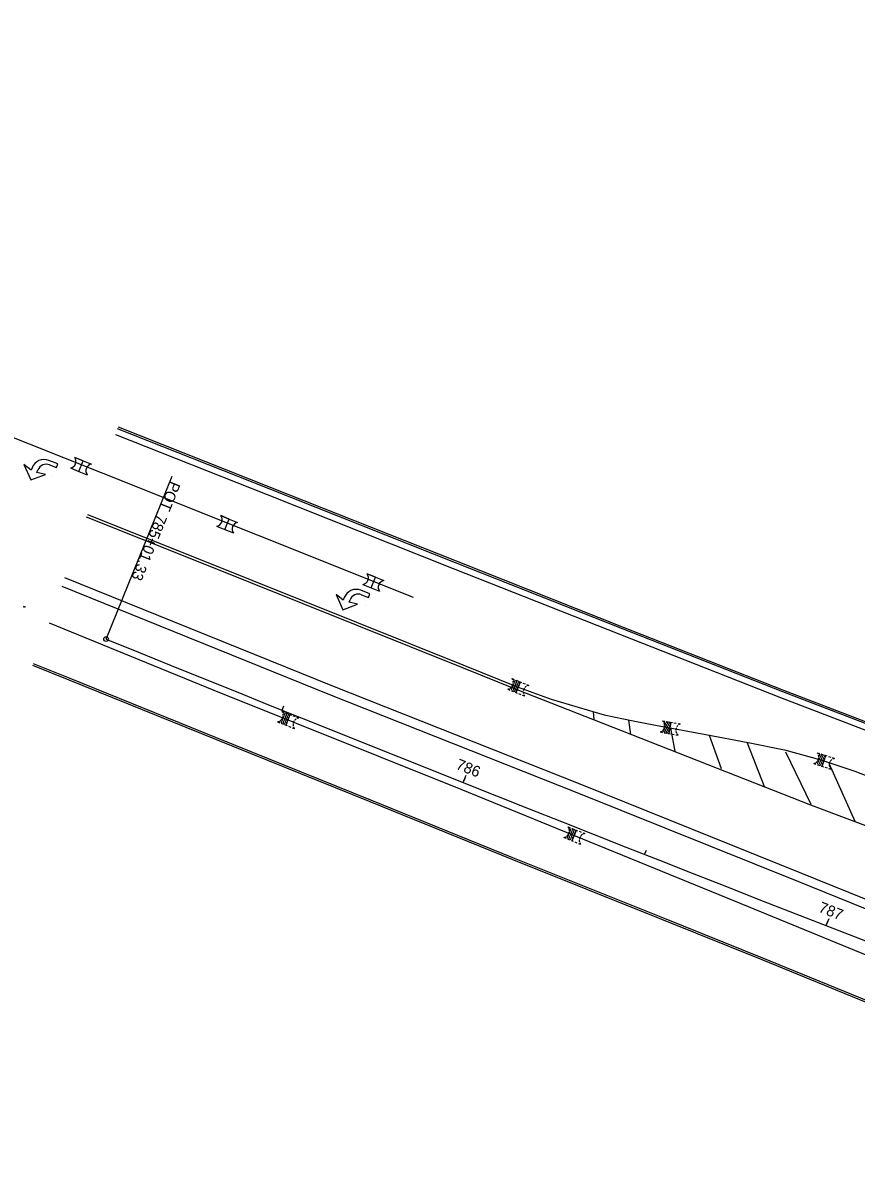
# Model space of a CAD drawing. Extents: x 2349621 to 2352073, y 625611 to 626553.
# Drawn here: x 2350953.7 to 2351167.3, y 625866.1 to 626159.2 of the extents above; entities that cross this region are included whole.
import ezdxf

# ---------------------------------------------------------------- set-up
doc = ezdxf.new("R2010")
doc.units = 0
for name, color, linetype in [('DR_P_Storm_Sewer', 7, 'Continuous'), ('MT_P_Dotted_Line', 7, 'Continuous'), ('PM_X_Cells', 7, 'Continuous'), ('PM_X_Channelizing_Line', 7, 'Continuous'), ('PM_X_Edge_Line', 7, 'Continuous'), ('PM_X_Lane_Line', 7, 'Continuous'), ('PV_X_Curb', 7, 'Continuous'), ('PV_X_EOP', 7, 'Continuous'), ('RW_X_CL', 7, 'Continuous'), ('RW_X_CL_1000_Cardinal_Points', 7, 'Continuous'), ('RW_X_CL_100_Cardinal_Points', 7, 'Continuous'), ('RW_X_CL_100_Stations', 7, 'Continuous'), ('RW_X_CL_500_Cardinal_Points', 7, 'Continuous'), ('RW_X_CL_500_Stations', 7, 'Continuous')]:
    doc.layers.add(name, color=color, linetype=linetype)

msp = doc.modelspace()

# ---------------------------------------------------------------- linework, layer by layer
at = {"layer": 'DR_P_Storm_Sewer'}
for p, q in [((2350953.99, 626046.04), (2350953.99, 626046.04)), ((2350955.83, 626044.6), (2350953.99, 626046.04)), ((2350953.99, 626046.04), (2350955.72, 626042.14)), ((2350962.66, 626046.21), (2350960.35, 626047.12)), ((2350960.56, 626045.97), (2350962.29, 626045.28)), ((2350962.29, 626045.28), (2350962.66, 626046.21)), ((2350969.15, 626047.03), (2350967.01, 626047.9)), ((2350967.01, 626047.9), (2350969.15, 626047.03)), ((2350968.05, 626044.31), (2350969.15, 626047.03)), ((2350969.15, 626047.03), (2350971.3, 626046.16)), ((2350955.72, 626042.14), (2350959.53, 626043.51)), ((2350956.08, 626045.22), (2350955.83, 626044.6)), ((2350957.32, 626044.02), (2350957.58, 626044.67)), ((2350959.53, 626043.51), (2350957.32, 626044.02)), ((2350961.43, 626043.11), (2350961.43, 626043.11)), ((2350965.91, 626045.18), (2350968.05, 626044.31)), ((2350965.91, 626045.18), (2350968.05, 626044.31)), ((2350968.05, 626044.31), (2350970.2, 626043.44)), ((2351006.63, 626032.1), (2351004.48, 626032.97)), ((2351004.48, 626032.97), (2351006.63, 626032.1)), ((2351005.52, 626029.39), (2351006.63, 626032.1)), ((2351006.63, 626032.1), (2351008.77, 626031.23)), ((2351003.38, 626030.26), (2351005.52, 626029.39)), ((2351003.38, 626030.26), (2351005.52, 626029.39)), ((2351005.52, 626029.39), (2351007.67, 626028.52)), ((2351044.1, 626017.18), (2351041.95, 626018.05)), ((2351041.95, 626018.05), (2351044.1, 626017.18)), ((2351043, 626014.46), (2351044.1, 626017.18)), ((2351044.1, 626017.18), (2351046.24, 626016.31)), ((2351042.66, 626012.95), (2351040.36, 626013.86)), ((2351040.85, 626015.33), (2351043, 626014.46)), ((2351040.85, 626015.33), (2351043, 626014.46)), ((2351043, 626014.46), (2351045.14, 626013.59)), ((2351034, 626012.78), (2351034, 626012.78)), ((2351035.84, 626011.34), (2351034, 626012.78)), ((2351034, 626012.78), (2351035.73, 626008.88)), ((2351036.08, 626011.96), (2351035.84, 626011.34)), ((2351037.33, 626010.76), (2351037.59, 626011.41)), ((2351039.53, 626010.25), (2351037.33, 626010.76)), ((2351040.56, 626012.71), (2351042.3, 626012.02)), ((2351042.3, 626012.02), (2351042.66, 626012.95)), ((2351035.73, 626008.88), (2351039.53, 626010.25)), ((2351041.44, 626009.85), (2351041.44, 626009.85))]:
    msp.add_line(p, q, dxfattribs=at)
for centre, radius, start, end in [((2350959.15, 626044.07), 3.28, 68.5035, 159.412), ((2350959.71, 626043.83), 2.3, 68.5035, 158.5035), ((2350965.61, 626046.88), 1.73, 279.8966, 35.9489), ((2350965.61, 626046.88), 1.73, 279.8966, 35.9489), ((2350971.59, 626044.46), 1.73, 99.8966, 215.9489), ((2351003.08, 626031.96), 1.73, 279.8966, 35.9489), ((2351003.08, 626031.96), 1.73, 279.8966, 35.9489), ((2351009.07, 626029.53), 1.73, 99.8966, 215.9489), ((2351040.56, 626017.03), 1.73, 279.8966, 35.9489), ((2351040.56, 626017.03), 1.73, 279.8966, 35.9489), ((2351039.16, 626010.81), 3.28, 68.5035, 159.412), ((2351046.54, 626014.61), 1.73, 99.8966, 215.9489), ((2351039.72, 626010.57), 2.3, 68.5035, 158.5035)]:
    msp.add_arc(centre, radius, start, end, dxfattribs=at)
at = {"layer": 'MT_P_Dotted_Line'}
msp.add_lwpolyline([(2350689.08, 626159.18), (2350751.11, 626134.18), (2350853.61, 626092.56), (2350906.16, 626071.18), (2350945.59, 626055.2), (2350974.18, 626043.81), (2351053.76, 626012.11)], dxfattribs=at)
at = {"layer": 'PM_X_Cells'}
for p, q in [((2351042.66, 626012.95), (2351040.36, 626013.86)), ((2351034, 626012.78), (2351034, 626012.78)), ((2351035.84, 626011.34), (2351034, 626012.78)), ((2351034, 626012.78), (2351035.73, 626008.88)), ((2351036.08, 626011.96), (2351035.84, 626011.34)), ((2351037.33, 626010.76), (2351037.59, 626011.41)), ((2351039.53, 626010.25), (2351037.33, 626010.76)), ((2351040.56, 626012.71), (2351042.3, 626012.02)), ((2351042.3, 626012.02), (2351042.66, 626012.95)), ((2350953.75, 626009.79), (2350954.31, 626009.57)), ((2351035.73, 626008.88), (2351039.53, 626010.25)), ((2351041.44, 626009.85), (2351041.44, 626009.85)), ((2351079.12, 625991.22), (2351079.67, 625991)), ((2351080.54, 625988.58), (2351079.49, 625991.07)), ((2351080.05, 625990.84), (2351080.61, 625990.62)), ((2351080.8, 625989.21), (2351080.12, 625990.82)), ((2351080.16, 625987.64), (2351081.26, 625990.35)), ((2351081.05, 625989.83), (2351080.74, 625990.56)), ((2351080.98, 625990.46), (2351081.54, 625990.24)), ((2351078.02, 625988.51), (2351078.57, 625988.28)), ((2351078.59, 625988.27), (2351078.43, 625988.63)), ((2351079.22, 625988.02), (2351078.84, 625988.9)), ((2351078.95, 625988.13), (2351079.51, 625987.9)), ((2351079.84, 625987.76), (2351079.19, 625989.3)), ((2351080.29, 625987.95), (2351079.43, 625989.97)), ((2351079.88, 625987.75), (2351080.44, 625987.52)), ((2351080.71, 625988.99), (2351080.71, 625988.99)), ((2351080.81, 625987.37), (2351081.37, 625987.15)), ((2351081.92, 625990.09), (2351082.47, 625989.86)), ((2351082.85, 625989.71), (2351083.4, 625989.48)), ((2351081.75, 625986.99), (2351082.3, 625986.77)), ((2351020.12, 625982.87), (2351020.68, 625982.65)), ((2351020.12, 625982.87), (2351020.68, 625982.65)), ((2351021.29, 625979.6), (2351020.44, 625981.62)), ((2351021.29, 625979.6), (2351020.44, 625981.62)), ((2351021.55, 625980.23), (2351020.49, 625982.72)), ((2351021.55, 625980.23), (2351020.49, 625982.72)), ((2351021.06, 625982.49), (2351021.61, 625982.27)), ((2351021.06, 625982.49), (2351021.61, 625982.27)), ((2351021.8, 625980.86), (2351021.12, 625982.47)), ((2351021.8, 625980.86), (2351021.12, 625982.47)), ((2351021.17, 625979.29), (2351022.27, 625982)), ((2351021.17, 625979.29), (2351022.27, 625982)), ((2351022.06, 625981.49), (2351021.75, 625982.21)), ((2351022.06, 625981.49), (2351021.75, 625982.21)), ((2351021.99, 625982.12), (2351022.55, 625981.89)), ((2351021.99, 625982.12), (2351022.55, 625981.89)), ((2351022.92, 625981.74), (2351023.48, 625981.51)), ((2351022.92, 625981.74), (2351023.48, 625981.51)), ((2351019.02, 625980.16), (2351019.58, 625979.93)), ((2351019.02, 625980.16), (2351019.58, 625979.93)), ((2351019.59, 625979.93), (2351019.44, 625980.29)), ((2351019.59, 625979.93), (2351019.44, 625980.29)), ((2351020.22, 625979.67), (2351019.85, 625980.55)), ((2351020.22, 625979.67), (2351019.85, 625980.55)), ((2351019.96, 625979.78), (2351020.51, 625979.55)), ((2351019.96, 625979.78), (2351020.51, 625979.55)), ((2351020.85, 625979.42), (2351020.2, 625980.96)), ((2351020.85, 625979.42), (2351020.2, 625980.96)), ((2351020.89, 625979.4), (2351021.44, 625979.18)), ((2351020.89, 625979.4), (2351021.44, 625979.18)), ((2351021.72, 625980.65), (2351021.72, 625980.65)), ((2351021.72, 625980.65), (2351021.72, 625980.65)), ((2351021.82, 625979.02), (2351022.38, 625978.8)), ((2351021.82, 625979.02), (2351022.38, 625978.8)), ((2351022.75, 625978.64), (2351023.31, 625978.42)), ((2351022.75, 625978.64), (2351023.31, 625978.42)), ((2351023.85, 625981.36), (2351024.41, 625981.13)), ((2351023.85, 625981.36), (2351024.41, 625981.13)), ((2351117.66, 625980.43), (2351118.25, 625980.32)), ((2351119.59, 625978.13), (2351118.05, 625980.36)), ((2351119.07, 625977.19), (2351118.12, 625978.57)), ((2351119.47, 625977.46), (2351118.22, 625979.27)), ((2351118.65, 625980.25), (2351119.24, 625980.14)), ((2351119.71, 625978.8), (2351118.72, 625980.23)), ((2351119.83, 625979.46), (2351119.39, 625980.11)), ((2351119.41, 625977.13), (2351119.93, 625980.01)), ((2351119.64, 625980.06), (2351120.23, 625979.96)), ((2351119.67, 625978.57), (2351119.67, 625978.57)), ((2351120.63, 625979.88), (2351121.22, 625979.77)), ((2351121.62, 625979.7), (2351122.21, 625979.59)), ((2351117.13, 625977.55), (2351117.72, 625977.44)), ((2351117.73, 625977.43), (2351117.51, 625977.76)), ((2351118.4, 625977.31), (2351117.86, 625978.1)), ((2351118.12, 625977.36), (2351118.71, 625977.26)), ((2351119.11, 625977.18), (2351119.7, 625977.07)), ((2351120.1, 625977), (2351120.69, 625976.89)), ((2351121.09, 625976.82), (2351121.68, 625976.71)), ((2351157.68, 625969.05), (2351157.25, 625969.9)), ((2351157.37, 625972.24), (2351157.94, 625972.05)), ((2351158.32, 625968.84), (2351157.57, 625970.33)), ((2351158.97, 625969.7), (2351157.74, 625972.11)), ((2351158.75, 625969.05), (2351157.76, 625971.01)), ((2351158.32, 625971.92), (2351158.89, 625971.74)), ((2351159.18, 625970.34), (2351158.39, 625971.9)), ((2351158.65, 625968.73), (2351159.56, 625971.52)), ((2351159.39, 625970.99), (2351159.03, 625971.69)), ((2351159.11, 625970.12), (2351159.11, 625970.12)), ((2351159.28, 625971.61), (2351159.85, 625971.42)), ((2351160.23, 625971.3), (2351160.8, 625971.11)), ((2351161.19, 625970.98), (2351161.76, 625970.8)), ((2351156.45, 625969.45), (2351157.02, 625969.27)), ((2351157.03, 625969.26), (2351156.86, 625969.61)), ((2351157.41, 625969.14), (2351157.98, 625968.95)), ((2351158.36, 625968.83), (2351158.93, 625968.64)), ((2351159.32, 625968.51), (2351159.89, 625968.33)), ((2351160.28, 625968.2), (2351160.85, 625968.01)), ((2351093.5, 625953.25), (2351094.05, 625953.03)), ((2351094.92, 625950.61), (2351093.87, 625953.1)), ((2351094.43, 625952.87), (2351094.99, 625952.65)), ((2351095.18, 625951.24), (2351094.5, 625952.85)), ((2351094.54, 625949.67), (2351095.64, 625952.38)), ((2351095.43, 625951.87), (2351095.12, 625952.59)), ((2351095.36, 625952.49), (2351095.92, 625952.27)), ((2351092.4, 625950.54), (2351092.95, 625950.31)), ((2351092.96, 625950.31), (2351092.81, 625950.66)), ((2351093.59, 625950.05), (2351093.22, 625950.93)), ((2351093.33, 625950.16), (2351093.88, 625949.93)), ((2351094.22, 625949.8), (2351093.57, 625951.33)), ((2351094.67, 625949.98), (2351093.81, 625952)), ((2351094.26, 625949.78), (2351094.82, 625949.55)), ((2351095.09, 625951.02), (2351095.09, 625951.02)), ((2351095.19, 625949.4), (2351095.75, 625949.18)), ((2351096.3, 625952.12), (2351096.85, 625951.89)), ((2351097.23, 625951.74), (2351097.78, 625951.51)), ((2351096.13, 625949.02), (2351096.68, 625948.8))]:
    msp.add_line(p, q, dxfattribs=at)
for centre, radius, start, end in [((2351039.16, 626010.81), 3.28, 68.5035, 159.412), ((2351039.72, 626010.57), 2.3, 68.5035, 158.5035), ((2350954.61, 626007.87), 1.73, 99.8966, 115.8391), ((2351077.72, 625990.21), 1.73, 20.0075, 35.9489), ((2351077.72, 625990.21), 1.73, 356.8106, 12.7435), ((2351077.72, 625990.21), 1.73, 279.8966, 295.8433), ((2351077.72, 625990.21), 1.73, 303.101, 319.0339), ((2351077.72, 625990.21), 1.73, 326.3132, 349.543), ((2351083.7, 625987.78), 1.73, 176.81, 192.7435), ((2351083.7, 625987.78), 1.73, 146.3043, 169.5319), ((2351083.7, 625987.78), 1.73, 123.101, 139.0326), ((2351083.7, 625987.78), 1.73, 99.8966, 115.8391), ((2351083.7, 625987.78), 1.73, 200.0045, 215.9489), ((2351018.73, 625981.86), 1.73, 20.0075, 35.9489), ((2351018.73, 625981.86), 1.73, 20.0075, 35.9489), ((2351018.73, 625981.86), 1.73, 326.3132, 349.543), ((2351018.73, 625981.86), 1.73, 326.3132, 349.543), ((2351018.73, 625981.86), 1.73, 356.8106, 12.7435), ((2351018.73, 625981.86), 1.73, 356.8106, 12.7435), ((2351018.73, 625981.86), 1.73, 279.8966, 295.8433), ((2351018.73, 625981.86), 1.73, 279.8966, 295.8433), ((2351018.73, 625981.86), 1.73, 303.101, 319.0339), ((2351018.73, 625981.86), 1.73, 303.101, 319.0339), ((2351024.71, 625979.43), 1.73, 176.81, 192.7435), ((2351024.71, 625979.43), 1.73, 176.81, 192.7435), ((2351024.71, 625979.43), 1.73, 146.3043, 169.5319), ((2351024.71, 625979.43), 1.73, 146.3043, 169.5319), ((2351024.71, 625979.43), 1.73, 200.0045, 215.9489), ((2351024.71, 625979.43), 1.73, 200.0045, 215.9489), ((2351024.71, 625979.43), 1.73, 123.101, 139.0326), ((2351024.71, 625979.43), 1.73, 123.101, 139.0326), ((2351024.71, 625979.43), 1.73, 99.8966, 115.8391), ((2351024.71, 625979.43), 1.73, 99.8966, 115.8391), ((2351116.5, 625979.15), 1.73, 31.6908, 47.6323), ((2351116.5, 625979.15), 1.73, 8.4939, 24.4269), ((2351116.5, 625979.15), 1.73, 337.9965, 1.2263), ((2351122.84, 625977.99), 1.73, 157.9877, 181.2153), ((2351122.84, 625977.99), 1.73, 134.7843, 150.7159), ((2351122.84, 625977.99), 1.73, 111.58, 127.5224), ((2351116.5, 625979.15), 1.73, 291.58, 307.5267), ((2351116.5, 625979.15), 1.73, 314.7843, 330.7172), ((2351122.84, 625977.99), 1.73, 188.4933, 204.4269), ((2351122.84, 625977.99), 1.73, 211.6879, 227.6323), ((2351156.04, 625971.13), 1.73, 307.0041, 322.937), ((2351156.04, 625971.13), 1.73, 23.9106, 39.852), ((2351156.04, 625971.13), 1.73, 330.2163, 353.4461), ((2351156.04, 625971.13), 1.73, 0.7137, 16.6466), ((2351162.17, 625969.12), 1.73, 150.2074, 173.435), ((2351162.17, 625969.12), 1.73, 127.0041, 142.9357), ((2351162.17, 625969.12), 1.73, 103.7997, 119.7422), ((2351156.04, 625971.13), 1.73, 283.7997, 299.7464), ((2351162.17, 625969.12), 1.73, 180.7131, 196.6466), ((2351162.17, 625969.12), 1.73, 203.9076, 219.852), ((2351092.1, 625952.24), 1.73, 20.0075, 35.9489), ((2351092.1, 625952.24), 1.73, 356.8106, 12.7435), ((2351092.1, 625952.24), 1.73, 279.8966, 295.8433), ((2351092.1, 625952.24), 1.73, 303.101, 319.0339), ((2351092.1, 625952.24), 1.73, 326.3132, 349.543), ((2351098.08, 625949.81), 1.73, 176.81, 192.7435), ((2351098.08, 625949.81), 1.73, 146.3043, 169.5319), ((2351098.08, 625949.81), 1.73, 200.0045, 215.9489), ((2351098.08, 625949.81), 1.73, 123.101, 139.0326), ((2351098.08, 625949.81), 1.73, 99.8966, 115.8391)]:
    msp.add_arc(centre, radius, start, end, dxfattribs=at)
at = {"layer": 'PM_X_Channelizing_Line'}
msp.add_line((2350974.18, 626043.81), (2351053.76, 626012.11), dxfattribs=at)
at = {"layer": 'PM_X_Edge_Line'}
for p, q in [((2351099.87, 625982.82), (2351100.11, 625980.67)), ((2351109.01, 625980.57), (2351109.52, 625976.91)), ((2351119.7, 625978.52), (2351120.88, 625972.65)), ((2351129.66, 625976.7), (2351132.75, 625968.19)), ((2351139.36, 625974.81), (2351143.8, 625963.42)), ((2351149.24, 625972.5), (2351155.71, 625959.06)), ((2351160.33, 625969.55), (2351166.98, 625954.67))]:
    msp.add_line(p, q, dxfattribs=at)
for points in [[(2350977.47, 626053.74), (2351016.31, 626038.35), (2351064.02, 626019.46), (2351106.89, 626002.49), (2351147.94, 625986.36), (2351202.99, 625965.26), (2351234.48, 625953.25), (2351287.27, 625933.36), (2351341.06, 625912.89), (2351383.66, 625897.13), (2351431.5, 625879.43), (2351486.97, 625859.09), (2351534.91, 625841.93), (2351586.59, 625823.19), (2351648.67, 625801.11), (2351691.59, 625785.98), (2351744.85, 625767.54), (2351787.37, 625752.87), (2351845.28, 625733.19), (2351909.09, 625711.34), (2351976.75, 625688.75)], [(2350970.27, 626033.22), (2350999, 626021.78), (2351066.48, 625994.71), (2351080.71, 625988.99), (2351089.12, 625985.94), (2351098.37, 625983.24), (2351102.77, 625981.98), (2351110.19, 625980.37), (2351115.88, 625979.26), (2351128.77, 625976.9), (2351139.63, 625974.85), (2351148.96, 625972.97), (2351158.3, 625970.39), (2351167.01, 625967.53), (2351200.24, 625954.65), (2351243.91, 625937.45), (2351284.31, 625921.78), (2351313.78, 625910.44), (2351344.1, 625898.66), (2351385.94, 625881.99)], [(2350963.74, 626014.89), (2351032.32, 625987.17), (2351095.71, 625962.07), (2351152.54, 625939.23), (2351209.68, 625916.15), (2351265.03, 625893.7), (2351303.58, 625877.76), (2351345.44, 625860.89), (2351387.6, 625843.99), (2351430.99, 625827.11), (2351474.75, 625810.9), (2351502.4, 625801.12), (2351535.69, 625789.35), (2351577.68, 625775.6), (2351622.58, 625760.66), (2351663.85, 625747.4), (2351714.74, 625729.84), (2351764.19, 625714.28), (2351799.77, 625703.13), (2351848.31, 625686.82), (2351889.58, 625673.56), (2351936.76, 625658.21), (2351982.15, 625643.49)], [(2351976.42, 625623.21), (2351920.83, 625640.97), (2351841.95, 625666.41), (2351777.12, 625687.69), (2351724.25, 625705.24), (2351652.33, 625728.98), (2351591.84, 625748.83), (2351555.08, 625760.87), (2351507.03, 625777.09), (2351478.29, 625787.21), (2351423.53, 625807.58), (2351365.19, 625830.22), (2351304.85, 625854.49), (2351247.93, 625877.37), (2351203.89, 625894.92), (2351143.43, 625919.65), (2351117.74, 625929.97), (2351079.36, 625945.33), (2351042.9, 625960.12), (2351003.33, 625976.06), (2350965.81, 625991.28), (2350956.45, 625995.04)]]:
    msp.add_lwpolyline(points, dxfattribs=at)
at = {"layer": 'PM_X_Lane_Line'}
msp.add_lwpolyline([(2350960.41, 626005.5), (2351002.64, 625988.3), (2351066, 625962.88), (2351136.34, 625934.22), (2351210.8, 625903.65), (2351315.64, 625861.8), (2351357.25, 625845.01), (2351429.58, 625816.81), (2351493.91, 625793.24), (2351605.6, 625755.44), (2351685.16, 625729.5), (2351789.05, 625695.46), (2351865.04, 625671.13), (2351976.54, 625634.71)], dxfattribs=at)
at = {"layer": 'PV_X_Curb'}
msp.add_lwpolyline([(2350978.14, 626055.68), (2351017.07, 626040.25), (2351064.77, 626021.37), (2351107.64, 626004.39), (2351148.68, 625988.27), (2351203.72, 625967.18), (2351235.21, 625955.17), (2351288, 625935.28), (2351341.78, 625914.81), (2351384.37, 625899.05), (2351432.2, 625881.35), (2351487.67, 625861.02), (2351535.61, 625843.86), (2351587.29, 625825.12), (2351649.36, 625803.04), (2351692.27, 625787.92), (2351745.52, 625769.48), (2351788.03, 625754.81), (2351845.94, 625735.13), (2351909.74, 625713.28), (2351977.4, 625690.7)], dxfattribs=at)
at = {"layer": 'PV_X_EOP'}
for points in [[(2351977.24, 625690.22), (2351909.58, 625712.81), (2351845.78, 625734.65), (2351787.87, 625754.34), (2351745.36, 625769.01), (2351692.1, 625787.45), (2351649.19, 625802.57), (2351587.12, 625824.65), (2351535.44, 625843.39), (2351487.5, 625860.55), (2351432.03, 625880.88), (2351384.2, 625898.58), (2351341.6, 625914.34), (2351287.82, 625934.81), (2351235.03, 625954.7), (2351203.54, 625966.71), (2351148.5, 625987.81), (2351107.45, 626003.93), (2351064.59, 626020.91), (2351016.88, 626039.79), (2350977.96, 626055.22)], [(2351381.54, 625873.89), (2351346.84, 625886.35), (2351302.15, 625902.96), (2351268.11, 625916.06), (2351222.23, 625933.47), (2351188.42, 625946.53), (2351155.74, 625958.79), (2351100.22, 625980.56), (2351080.46, 625988.33), (2351066.22, 625994.04), (2350998.74, 626021.12), (2350970.01, 626032.55)], [(2351982.85, 625645.63), (2351937.46, 625660.36), (2351890.28, 625675.71), (2351849.01, 625688.96), (2351800.47, 625705.27), (2351764.87, 625716.44), (2351715.44, 625731.98), (2351664.57, 625749.54), (2351623.28, 625762.81), (2351578.39, 625777.74), (2351536.41, 625791.49), (2351503.15, 625803.24), (2351475.52, 625813.02), (2351431.79, 625829.22), (2351388.43, 625846.09), (2351346.28, 625862.98), (2351304.44, 625879.85), (2351265.89, 625895.79), (2351210.53, 625918.24), (2351153.38, 625941.32), (2351096.55, 625964.17), (2351033.16, 625989.26), (2350964.49, 626017.02)], [(2351976.27, 625622.73), (2351920.68, 625640.49), (2351841.8, 625665.93), (2351776.97, 625687.21), (2351724.09, 625704.77), (2351652.18, 625728.51), (2351591.68, 625748.36), (2351554.93, 625760.4), (2351506.86, 625776.62), (2351478.12, 625786.74), (2351423.35, 625807.11), (2351365, 625829.75), (2351304.66, 625854.02), (2351247.74, 625876.9), (2351203.71, 625894.46), (2351143.24, 625919.19), (2351117.55, 625929.5), (2351079.17, 625944.86), (2351042.71, 625959.65), (2351003.14, 625975.6), (2350965.62, 625990.82), (2350956.27, 625994.57)]]:
    msp.add_lwpolyline(points, dxfattribs=at)
at = {"layer": 'RW_X_CL'}
msp.add_arc((2356442.68, 639481.86), 14547.12, 247.922783, 252.452173, dxfattribs=at)
at = {"layer": 'RW_X_CL_1000_Cardinal_Points'}
msp.add_line((2350975.06, 626001.36), (2350991.97, 626043.06), dxfattribs=at)
msp.add_circle((2350975.06, 626001.36), 0.6, dxfattribs=at)
at = {"layer": 'RW_X_CL_100_Cardinal_Points'}
msp.add_line((2350975.06, 626001.36), (2350991.97, 626043.06), dxfattribs=at)
msp.add_circle((2350975.06, 626001.36), 0.6, dxfattribs=at)
at = {"layer": 'RW_X_CL_100_Stations'}
for p, q in [((2351020.19, 625983.14), (2351020.64, 625984.26)), ((2351066.62, 625964.59), (2351067.36, 625966.45)), ((2351113.11, 625946.19), (2351113.55, 625947.3)), ((2351159.67, 625927.95), (2351160.39, 625929.81))]:
    msp.add_line(p, q, dxfattribs=at)
at = {"layer": 'RW_X_CL_500_Cardinal_Points'}
msp.add_line((2350975.06, 626001.36), (2350991.97, 626043.06), dxfattribs=at)
msp.add_circle((2350975.06, 626001.36), 0.6, dxfattribs=at)
at = {"layer": 'RW_X_CL_500_Stations'}
for p, q in [((2351066.62, 625964.59), (2351067.06, 625965.7)), ((2351159.67, 625927.95), (2351160.1, 625929.07))]:
    msp.add_line(p, q, dxfattribs=at)

# ---------------------------------------------------------------- texts
at = {"layer": 'RW_X_CL_1000_Cardinal_Points'}
for s, p in [('POT', (2350991.59, 626041.99)), ('785+01.33', (2350988.16, 626033.53))]:
    msp.add_text(s, height=2.8, rotation=247.9228, dxfattribs=at).set_placement(p)
at = {"layer": 'RW_X_CL_100_Cardinal_Points'}
for s, p in [('POT', (2350991.59, 626041.99)), ('785+01.33', (2350988.16, 626033.53))]:
    msp.add_text(s, height=2.8, rotation=247.9228, dxfattribs=at).set_placement(p)
at = {"layer": 'RW_X_CL_100_Stations'}
for s, rotation, p in [('786', 338.3114, (2351064.51, 625968.17)), ('787', 338.7053, (2351157.48, 625931.54))]:
    msp.add_text(s, height=2.8, rotation=rotation, dxfattribs=at).set_placement(p)
at = {"layer": 'RW_X_CL_500_Cardinal_Points'}
for s, p in [('POT', (2350991.59, 626041.99)), ('785+01.33', (2350988.16, 626033.53))]:
    msp.add_text(s, height=2.8, rotation=247.9228, dxfattribs=at).set_placement(p)

doc.saveas('drawing.dxf')
